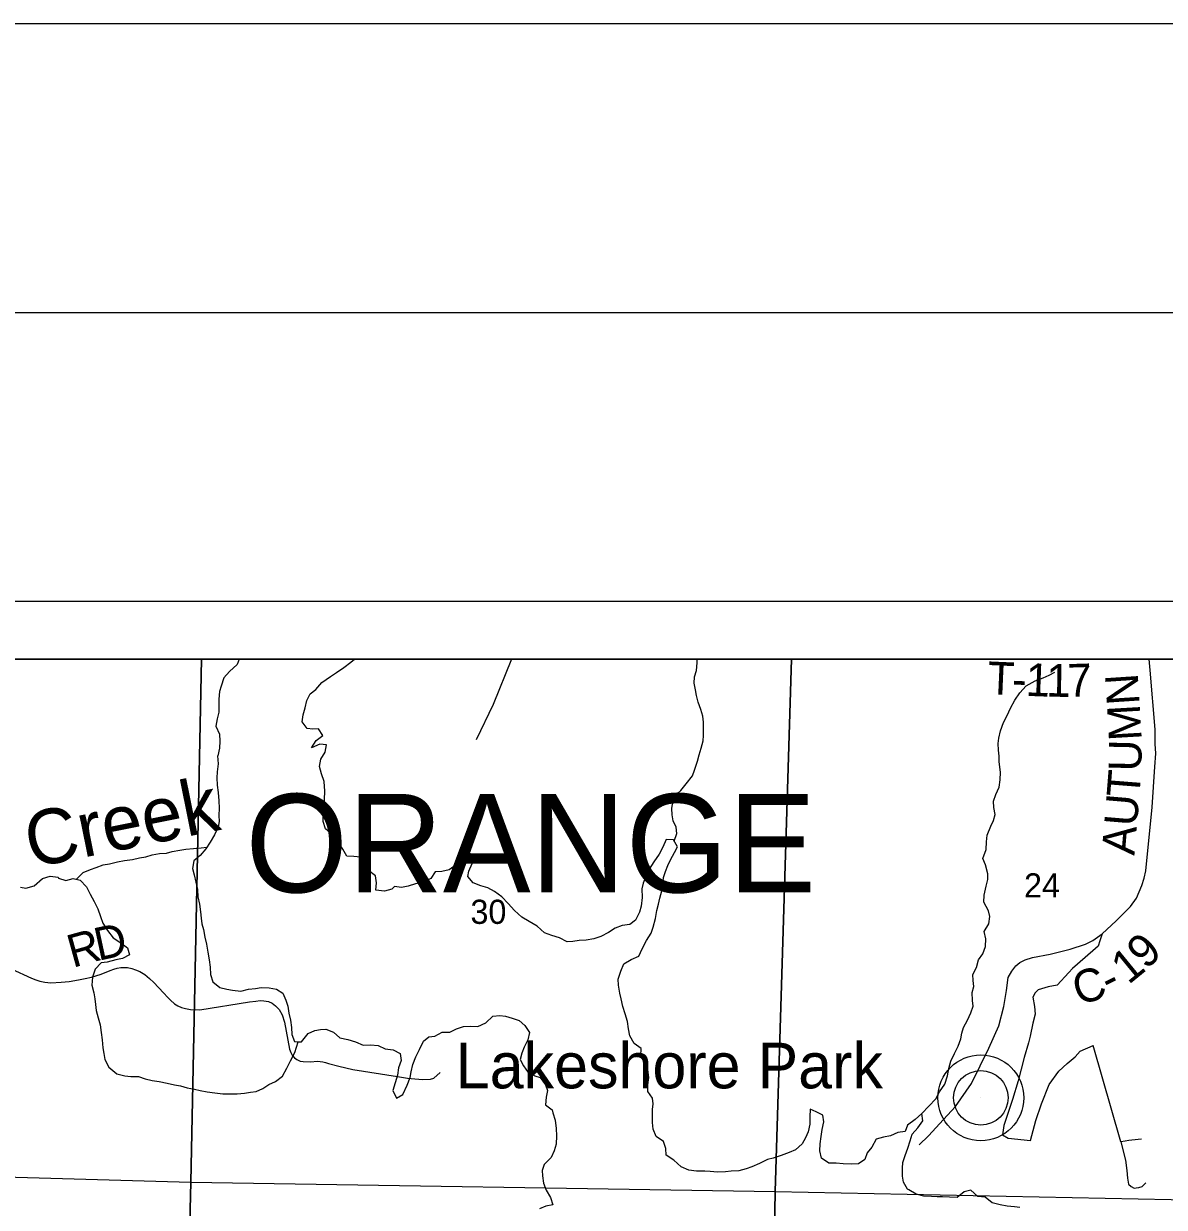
# Model space of a CAD drawing. Extents: x 0 to 34, y 0 to 22.
# Drawn here: x 4.316 to 6.292, y 19.951 to 22 of the extents above; entities that cross this region are included whole.
import ezdxf

# ---------------------------------------------------------------- set-up
doc = ezdxf.new("R2010")
doc.units = 0
for name, color, linetype in [('Default', 7, 'Continuous'), ('GM_X_Corporation', 7, 'Continuous'), ('GM_X_Corporation_Text', 7, 'Continuous'), ('GM_X_County_Road_Text', 7, 'Continuous'), ('GM_X_Interchange_Ramps', 7, 'Continuous'), ('GM_X_Interstate_Route', 7, 'Continuous'), ('GM_X_Major_Lake', 7, 'Continuous'), ('GM_X_Major_River', 7, 'Continuous'), ('GM_X_Minor_Lake', 7, 'Continuous'), ('GM_X_Section', 7, 'Continuous'), ('GM_X_Section_Text', 7, 'Continuous'), ('GM_X_State_Location', 7, 'Continuous'), ('GM_X_State_Shield', 7, 'Continuous'), ('GM_X_Township_Road_Text', 7, 'Continuous'), ('GM_X_Unincorporated_Location', 7, 'Continuous'), ('GM_X_US_Location', 7, 'Continuous'), ('SH_Border', 7, 'Continuous'), ('SH_Cut_Line', 7, 'Continuous'), ('SH_Data', 7, 'Continuous')]:
    doc.layers.add(name, color=color, linetype=linetype)

msp = doc.modelspace()

# ---------------------------------------------------------------- linework, layer by layer
at = {"layer": 'Default'}
for points in [[(4.6239, 20.9), (3.7753, 20.9), (3.7556, 20.0185), (4.6053, 19.9945)], [(5.6459, 20.9), (4.6239, 20.9), (4.6053, 19.9945), (5.6176, 19.9781)], [(6.6727, 20.9), (5.6459, 20.9), (5.6176, 19.9781), (6.6462, 19.9578)]]:
    msp.add_lwpolyline(points, close=True, dxfattribs=at)
at = {"layer": 'GM_X_Corporation'}
msp.add_lwpolyline([(5.8668, 20.0593), (5.8829, 20.0744), (5.9091, 20.103), (5.93, 20.1254), (5.9573, 20.1651), (5.9874, 20.2262), (6.0048, 20.265), (6.0134, 20.2985), (6.0184, 20.3265), (6.0212, 20.3488), (6.0273, 20.36), (6.0346, 20.369), (6.0415, 20.3747), (6.0504, 20.3794), (6.0631, 20.3834), (6.094, 20.389), (6.1284, 20.3979), (6.1552, 20.4067), (6.1675, 20.4131), (6.1757, 20.4188), (6.1841, 20.4246), (6.2081, 20.447), (6.233, 20.4716), (6.2431, 20.4859), (6.248, 20.4973), (6.2524, 20.508), (6.2565, 20.5207), (6.2594, 20.5336), (6.2705, 20.6434), (6.2749, 20.7136), (6.2765, 20.7368), (6.2759, 20.7531), (6.2755, 20.7781), (6.2668, 20.8811), (6.2652, 20.9)], dxfattribs=at)
at = {"layer": 'GM_X_Interchange_Ramps'}
msp.add_lwpolyline([(6.6698, 20.9), (2.1, 20.9), (2.1, 17.9098), (2.4376, 17.9025), (2.6711, 17.8975), (2.9484, 17.8857), (3.604, 17.8577), (3.7063, 17.8588), (3.7128, 17.9822), (4.1825, 17.9744), (4.4481, 17.9728), (4.5919, 17.9719), (4.9267, 17.9702), (4.9368, 17.9702), (4.994, 17.969), (5.3871, 17.9608), (5.6339, 17.9555), (6.0729, 17.9463), (6.24, 17.9427), (6.5943, 17.9356), (6.6079, 18.3189), (6.6258, 18.9603), (6.6304, 19.2166), (6.6438, 19.9593)], close=True, dxfattribs=at)
at = {"layer": 'GM_X_Interstate_Route'}
for points in [[(5.1608, 20.9), (5.1293, 20.8215), (5.0999, 20.7602)], [(6.1841, 20.4246), (6.1796, 20.4124), (6.177, 20.4031), (6.1676, 20.3948), (6.1324, 20.3644), (6.1262, 20.3577)], [(4.2946, 20.3639), (4.3294, 20.3474), (4.3372, 20.3446), (4.344, 20.3424), (4.3527, 20.3406), (4.3628, 20.3395), (4.3812, 20.3406), (4.3947, 20.342), (4.4107, 20.3448), (4.4225, 20.347), (4.4333, 20.3495), (4.4505, 20.3547), (4.4659, 20.361), (4.4722, 20.363), (4.4778, 20.3648), (4.4842, 20.366), (4.4902, 20.3662), (4.4961, 20.366), (4.5031, 20.3645), (4.5096, 20.3623), (4.517, 20.359), (4.5256, 20.3537), (4.534, 20.3472), (4.5413, 20.3402), (4.5583, 20.3222), (4.5658, 20.3141), (4.5701, 20.3095), (4.5771, 20.3031), (4.583, 20.3), (4.5896, 20.297), (4.5963, 20.2949), (4.6052, 20.2933), (4.6213, 20.293), (4.7073, 20.3067), (4.718, 20.3081), (4.7254, 20.3088), (4.732, 20.3084), (4.7399, 20.307), (4.7464, 20.3042), (4.7523, 20.3), (4.7586, 20.2932), (4.7638, 20.2844), (4.7679, 20.2713), (4.7764, 20.2246), (4.7786, 20.2188), (4.7812, 20.2142), (4.7848, 20.2097), (4.7889, 20.2067), (4.7946, 20.2041), (4.8, 20.2031), (4.8124, 20.2029), (4.8252, 20.2037), (4.8298, 20.2036), (4.8341, 20.203), (4.8386, 20.2019), (4.8442, 20.2001), (4.8619, 20.1952), (4.886, 20.1898), (4.9632, 20.1775), (4.9808, 20.1743), (4.9936, 20.1732), (5.0073, 20.1722), (5.0204, 20.1729), (5.0263, 20.1743), (5.0373, 20.1846)], [(6.1262, 20.3577), (6.1057, 20.3355), (6.0903, 20.3328), (6.0732, 20.3272), (6.0676, 20.3223), (6.0637, 20.3147), (6.0666, 20.2986), (6.0679, 20.2852), (6.064, 20.2697), (6.0594, 20.247), (6.056, 20.2356)], [(6.056, 20.2356), (6.0485, 20.2102), (6.0383, 20.1697), (6.0288, 20.1378), (6.0189, 20.1079), (6.0134, 20.0928), (6.011, 20.0764), (6.0212, 20.0708), (6.06, 20.0668)], [(6.06, 20.0668), (6.0689, 20.1013), (6.0788, 20.1303), (6.0923, 20.1638), (6.109, 20.1868), (6.1235, 20.1997), (6.137, 20.2115), (6.1455, 20.221), (6.1685, 20.2312)], [(6.2521, 20.0691), (6.235, 20.0671), (6.23, 20.0665), (6.2238, 20.0655), (6.2159, 20.0645), (6.1685, 20.2312)], [(6.2159, 20.0645), (6.2241, 20.0323), (6.2264, 20.0145), (6.2276, 20.0016), (6.2286, 19.9946), (6.2295, 19.991), (6.2339, 19.9867), (6.2395, 19.9838), (6.2429, 19.9848), (6.2476, 19.9853), (6.2529, 19.9872), (6.2568, 19.9904), (6.2595, 19.9935)]]:
    msp.add_lwpolyline(points, dxfattribs=at)
at = {"layer": 'GM_X_Minor_Lake'}
for points in [[(3.7556, 20.0185), (4.6053, 19.9945), (4.5812, 18.9996), (3.7421, 19.0151), (3.7574, 19.9211)], [(4.6053, 19.9945), (5.6176, 19.9781), (5.6006, 18.9822), (4.5812, 18.9996)], [(6.6462, 19.9578), (6.6311, 18.9612), (5.6006, 18.9822), (5.6176, 19.9781)]]:
    msp.add_lwpolyline(points, close=True, dxfattribs=at)
at = {"layer": 'GM_X_State_Location'}
msp.add_line((5.9737, 20.1405), (5.9737, 20.1405), dxfattribs=at)
at = {"layer": 'GM_X_State_Shield'}
for radius in [0.0744, 0.0472]:
    msp.add_circle((5.9737, 20.1405), radius, dxfattribs=at)
at = {"layer": 'GM_X_Township_Road_Text'}
for points in [[(5.4428, 20.5847), (5.4474, 20.5979), (5.4458, 20.6089), (5.4411, 20.6198), (5.4391, 20.6301), (5.4383, 20.6414), (5.4401, 20.6525), (5.4434, 20.6627), (5.454, 20.6723), (5.4634, 20.6838), (5.4743, 20.6979), (5.478, 20.7078), (5.4828, 20.7234), (5.4861, 20.734), (5.4894, 20.7458), (5.4931, 20.7584), (5.4934, 20.7678), (5.4932, 20.791), (5.4923, 20.8012), (5.4888, 20.8126), (5.4841, 20.8254), (5.481, 20.8372), (5.4798, 20.8466), (5.4774, 20.8584), (5.4781, 20.869), (5.481, 20.8804), (5.4824, 20.8937), (5.4824, 20.9)], [(5.8713, 20.1131), (5.8838, 20.1263), (5.8959, 20.1389), (5.9019, 20.1507), (5.9112, 20.1644), (5.916, 20.1785), (5.9182, 20.1914), (5.9215, 20.204), (5.9282, 20.2173), (5.9342, 20.2299), (5.939, 20.2428), (5.9408, 20.2523), (5.9434, 20.2622), (5.9509, 20.2752), (5.9565, 20.2877), (5.9606, 20.2992), (5.9593, 20.309), (5.9585, 20.3227), (5.9618, 20.3333), (5.9606, 20.3435), (5.9601, 20.3542), (5.9661, 20.366), (5.9697, 20.3793), (5.9772, 20.3896), (5.9817, 20.4025), (5.9823, 20.4158), (5.9796, 20.4287), (5.9878, 20.4416), (5.9892, 20.4546), (5.9868, 20.4644), (5.9791, 20.4791), (5.9794, 20.4913), (5.983, 20.5069), (5.9856, 20.5183), (5.9859, 20.5285), (5.9816, 20.5436), (5.9773, 20.555), (5.9829, 20.5702), (5.9835, 20.5835), (5.9845, 20.5953), (5.9913, 20.6109), (5.9957, 20.6208), (5.9983, 20.631), (5.9963, 20.6428), (5.9958, 20.6538), (5.9999, 20.6656), (6.0055, 20.6785), (6.0073, 20.6907), (6.0075, 20.7043), (6.0055, 20.7221), (6.0054, 20.732), (6.0041, 20.7422), (6.004, 20.7536), (6.0051, 20.7631), (6.0076, 20.776), (6.0132, 20.7901), (6.0192, 20.8023), (6.0252, 20.8149), (6.0326, 20.8286), (6.0413, 20.8416), (6.0525, 20.8538), (6.068, 20.8626), (6.0817, 20.8677), (6.0923, 20.8723), (6.1021, 20.8774)], [(4.4074, 20.5188), (4.419, 20.5305), (4.4315, 20.5359), (4.4413, 20.539), (4.4538, 20.5437), (4.4648, 20.5453), (4.4785, 20.5492), (4.4906, 20.5516), (4.5046, 20.5532), (4.5168, 20.5559), (4.5274, 20.5579), (4.5387, 20.5614), (4.5513, 20.5634), (4.5634, 20.5643), (4.5733, 20.567), (4.5865, 20.5691), (4.5968, 20.571), (4.6101, 20.5723), (4.6237, 20.5732), (4.6334, 20.5745)]]:
    msp.add_lwpolyline(points, dxfattribs=at)
at = {"layer": 'GM_X_Unincorporated_Location'}
for points in [[(4.6892, 20.9), (4.6856, 20.8905), (4.6725, 20.8785), (4.6628, 20.8674), (4.6581, 20.8533), (4.6552, 20.8437), (4.6543, 20.8304), (4.654, 20.821), (4.6543, 20.8084), (4.651, 20.7963), (4.649, 20.7841), (4.6553, 20.7701), (4.6559, 20.758), (4.6549, 20.7459), (4.6521, 20.7325)], [(4.8123, 20.8399), (4.822, 20.8476), (4.8324, 20.8595), (4.8475, 20.87), (4.8576, 20.8766), (4.8704, 20.8852), (4.8824, 20.8949), (4.8892, 20.9)], [(4.9536, 20.5019), (4.9408, 20.4983), (4.9259, 20.4999), (4.9268, 20.5125), (4.9255, 20.5246), (4.9135, 20.5343), (4.9073, 20.5459), (4.8995, 20.5572), (4.888, 20.5581), (4.8759, 20.5591), (4.8688, 20.5707), (4.8606, 20.5831), (4.8509, 20.5958), (4.8386, 20.6059), (4.835, 20.6187), (4.8347, 20.6324), (4.8357, 20.6441), (4.837, 20.657), (4.8375, 20.6711), (4.8365, 20.6878), (4.8321, 20.7013), (4.8284, 20.7138), (4.8305, 20.7267), (4.8383, 20.739), (4.8403, 20.7516), (4.8289, 20.7529), (4.8146, 20.7462), (4.8227, 20.7592), (4.834, 20.7678), (4.8266, 20.7794), (4.8171, 20.7785), (4.8072, 20.7798), (4.7986, 20.7915), (4.8003, 20.8036), (4.8035, 20.8158), (4.8067, 20.8284), (4.8123, 20.8399)], [(4.6521, 20.7325), (4.6517, 20.7325), (4.6527, 20.7189), (4.6514, 20.7048), (4.6508, 20.6946), (4.6514, 20.6817), (4.6528, 20.6688), (4.6542, 20.6548), (4.6544, 20.6419), (4.6542, 20.629), (4.6544, 20.6191), (4.6527, 20.6089), (4.6468, 20.5959), (4.639, 20.5832), (4.6316, 20.5717), (4.6219, 20.5598), (4.611, 20.5509), (4.6086, 20.5376), (4.6115, 20.5263), (4.6143, 20.5138), (4.6168, 20.5013), (4.6174, 20.4884), (4.6203, 20.4759), (4.622, 20.4627), (4.6234, 20.4513), (4.6247, 20.4415), (4.6275, 20.4317), (4.63, 20.4188), (4.6325, 20.4063), (4.635, 20.3927), (4.6371, 20.3795), (4.6388, 20.3666), (4.6398, 20.3541), (4.6438, 20.3413), (4.6558, 20.3312), (4.668, 20.3288), (4.6775, 20.3267), (4.6924, 20.325), (4.7056, 20.3283), (4.7174, 20.33), (4.7276, 20.3313), (4.7413, 20.3307), (4.7539, 20.3287), (4.765, 20.3216), (4.7698, 20.3096), (4.7734, 20.299), (4.7755, 20.2873), (4.7784, 20.2752), (4.7801, 20.262), (4.7807, 20.2502), (4.7851, 20.2378), (4.7914, 20.2375)], [(5.4423, 20.0327), (5.4289, 20.0412), (5.4283, 20.053), (5.4239, 20.065), (5.4112, 20.0736), (5.4065, 20.086), (5.4051, 20.0977), (5.4049, 20.1099), (5.4051, 20.1205), (5.4061, 20.13), (5.4052, 20.1398), (5.397, 20.1515), (5.3972, 20.1632), (5.3989, 20.1758), (5.3972, 20.1887), (5.3916, 20.1999), (5.385, 20.2131), (5.3855, 20.2256), (5.3736, 20.2345), (5.3661, 20.2477), (5.3633, 20.2598), (5.3615, 20.2727), (5.3579, 20.2859), (5.3539, 20.2983), (5.3506, 20.3119), (5.3486, 20.3218), (5.346, 20.3354), (5.3459, 20.346), (5.3502, 20.3597), (5.3553, 20.3723), (5.3681, 20.3801), (5.3813, 20.3857), (5.3872, 20.3986), (5.3946, 20.4128), (5.4027, 20.4258), (5.4063, 20.4358), (5.4103, 20.451), (5.4127, 20.4647), (5.4152, 20.4757), (5.4177, 20.4864), (5.4212, 20.499), (5.423, 20.5085), (5.4243, 20.5218), (5.4275, 20.5321), (5.4315, 20.5428), (5.4363, 20.5527), (5.4433, 20.5653), (5.4485, 20.5749), (5.4414, 20.5869), (5.4289, 20.5879), (5.423, 20.5745), (5.4168, 20.5623), (5.4071, 20.5488), (5.3993, 20.5362), (5.3935, 20.5239), (5.3887, 20.5121), (5.3866, 20.5022), (5.3869, 20.487), (5.3852, 20.4722), (5.3823, 20.4619), (5.3757, 20.4482), (5.3656, 20.4408), (5.3527, 20.4387), (5.3406, 20.4339), (5.3286, 20.4269), (5.3154, 20.4195), (5.3033, 20.4155), (5.2904, 20.4137), (5.2782, 20.4128), (5.2669, 20.4111), (5.2574, 20.4105), (5.2443, 20.4175), (5.2306, 20.4215), (5.2179, 20.4262), (5.2052, 20.4374), (5.1914, 20.4459), (5.1787, 20.4533), (5.166, 20.4648), (5.1551, 20.4771), (5.1443, 20.4883), (5.1316, 20.4976), (5.1201, 20.5039), (5.1075, 20.5075), (5.0945, 20.5126), (5.0855, 20.5234), (5.0869, 20.5329), (5.0928, 20.5459), (5.1002, 20.5589), (5.0902, 20.5626), (5.0767, 20.554), (5.0669, 20.5447), (5.053, 20.5354), (5.0405, 20.5325), (5.0288, 20.5316), (5.0214, 20.5201), (5.0085, 20.5138), (4.9945, 20.5109), (4.9817, 20.5069), (4.9703, 20.5048), (4.9581, 20.5062), (4.9536, 20.5019)], [(4.7914, 20.2375), (4.7972, 20.2372), (4.8088, 20.2518), (4.8205, 20.2569), (4.8299, 20.2586), (4.8394, 20.2595), (4.8528, 20.254), (4.8636, 20.2444), (4.8774, 20.2415), (4.8907, 20.2376), (4.9041, 20.2317), (4.9167, 20.232), (4.93, 20.231), (4.9423, 20.2255), (4.956, 20.2235), (4.9679, 20.2172), (4.97, 20.2051), (4.9653, 20.1922), (4.9636, 20.1796), (4.9596, 20.1666), (4.9556, 20.1529), (4.9619, 20.1397), (4.9725, 20.1464), (4.9802, 20.1624), (4.9853, 20.1758), (4.987, 20.1853), (4.9899, 20.1979), (4.995, 20.2116), (5.0016, 20.2239), (5.0082, 20.2384), (5.0179, 20.2461), (5.0282, 20.2474), (5.0406, 20.2541), (5.0539, 20.2543), (5.0656, 20.2602), (5.0777, 20.2638), (5.0895, 20.2644), (5.1024, 20.2642), (5.1164, 20.2705), (5.1287, 20.2817), (5.1409, 20.2831), (5.1504, 20.2821), (5.1622, 20.2785), (5.1741, 20.2741), (5.1841, 20.2659), (5.1919, 20.2536), (5.1891, 20.2406), (5.1829, 20.228), (5.1785, 20.218), (5.176, 20.2066), (5.1819, 20.1961)], [(5.1819, 20.1961), (5.19, 20.1845), (5.2012, 20.1786), (5.2107, 20.1757), (5.2197, 20.163), (5.2233, 20.1532), (5.2212, 20.1417), (5.2195, 20.1284), (5.2314, 20.1195)], [(5.2314, 20.1195), (5.2323, 20.1146), (5.2363, 20.1018), (5.238, 20.0874), (5.2386, 20.0749), (5.2385, 20.0605), (5.2349, 20.0486), (5.2298, 20.0372), (5.2174, 20.0252), (5.2138, 20.0149), (5.2143, 20.0054), (5.2161, 19.9926), (5.2212, 19.9809), (5.2282, 19.9681), (5.2323, 19.9553), (5.2201, 19.9532), (5.2092, 19.9481)], [(5.8465, 19.9821), (5.8399, 19.9942), (5.8378, 20.0051), (5.8379, 20.0188), (5.8389, 20.0283), (5.8429, 20.0405), (5.8472, 20.0535), (5.8516, 20.0661), (5.8548, 20.0775), (5.8645, 20.0887), (5.8731, 20.1006), (5.8713, 20.1131), (5.8597, 20.103), (5.8466, 20.0933), (5.8429, 20.0822), (5.8301, 20.0805), (5.8172, 20.0746), (5.8051, 20.0725), (5.7926, 20.0689), (5.7852, 20.0551), (5.777, 20.0455), (5.7727, 20.034), (5.7618, 20.0263), (5.7492, 20.0257), (5.7352, 20.0262), (5.7234, 20.0275), (5.7104, 20.0273), (5.6977, 20.0362), (5.6949, 20.0487), (5.6954, 20.0608), (5.6971, 20.0737), (5.6992, 20.0859), (5.702, 20.0989), (5.6999, 20.1102), (5.6888, 20.1165), (5.6781, 20.1208), (5.6775, 20.1076), (5.6778, 20.0947), (5.6745, 20.0817), (5.6702, 20.071), (5.6643, 20.0611), (5.6526, 20.0502), (5.6417, 20.0459), (5.6281, 20.0407), (5.6141, 20.0359), (5.6043, 20.0335), (5.5903, 20.0268), (5.5771, 20.0213), (5.5673, 20.0177), (5.5544, 20.0141), (5.5411, 20.0135), (5.5313, 20.0122), (5.5176, 20.012), (5.505, 20.0129), (5.4955, 20.0135), (5.481, 20.0136), (5.4681, 20.0153), (5.4547, 20.0208), (5.4423, 20.0327)], [(6.0413, 19.9505), (6.0318, 19.9515), (6.0192, 19.9532), (6.007, 19.9552), (5.9933, 19.9588), (5.9813, 19.9685), (5.9684, 19.9698), (5.9564, 19.9809), (5.9447, 19.9777), (5.9327, 19.968), (5.9197, 19.9686), (5.9076, 19.9691), (5.8981, 19.969), (5.8885, 19.9699), (5.8752, 19.9701), (5.8619, 19.9737), (5.8492, 19.981), (5.8465, 19.9821)]]:
    msp.add_lwpolyline(points, dxfattribs=at)
at = {"layer": 'GM_X_US_Location'}
for points in [[(4.3104, 20.505), (4.3199, 20.5032), (4.3343, 20.5073), (4.3485, 20.5204), (4.3621, 20.5244), (4.3755, 20.5224)], [(4.3755, 20.5224), (4.3763, 20.5205), (4.3889, 20.5165), (4.4017, 20.5201), (4.4139, 20.5173), (4.4248, 20.5057), (4.4314, 20.4933), (4.4381, 20.4802), (4.4444, 20.4674), (4.4488, 20.4542), (4.4532, 20.4428), (4.461, 20.4301), (4.4711, 20.4177), (4.4826, 20.4099), (4.4957, 20.3999), (4.4993, 20.3882), (4.4869, 20.3816), (4.4759, 20.3791), (4.4604, 20.3754), (4.4505, 20.3741), (4.4401, 20.363), (4.4354, 20.3492), (4.4341, 20.3355), (4.4373, 20.3223), (4.439, 20.3117), (4.4403, 20.3019), (4.4417, 20.2917), (4.4449, 20.2792), (4.4485, 20.2671), (4.4503, 20.2535), (4.452, 20.241), (4.4534, 20.227), (4.4551, 20.2171), (4.4564, 20.2069), (4.4634, 20.1938), (4.4773, 20.1822), (4.4914, 20.1787), (4.5017, 20.1773), (4.5147, 20.1772), (4.5265, 20.1732), (4.5387, 20.1707), (4.5505, 20.1686), (4.5643, 20.1658), (4.5772, 20.163), (4.5879, 20.1613), (4.599, 20.1577), (4.6116, 20.1556), (4.6219, 20.1531), (4.6337, 20.1507), (4.647, 20.149), (4.6611, 20.1473), (4.6741, 20.1472), (4.6858, 20.1473), (4.6987, 20.1487), (4.7086, 20.15), (4.7185, 20.1517), (4.7302, 20.1568), (4.7407, 20.1634), (4.752, 20.1689), (4.764, 20.1782), (4.7718, 20.1916), (4.7784, 20.2043), (4.7858, 20.2188), (4.7886, 20.2283), (4.7914, 20.2375)]]:
    msp.add_lwpolyline(points, dxfattribs=at)
at = {"layer": 'SH_Border'}
msp.add_lwpolyline([(1.5, 21.5), (33.5, 21.5), (33.5, 0.5), (1.5, 0.5)], close=True, dxfattribs=at)
at = {"layer": 'SH_Cut_Line'}
for points in [[(0, 0), (34, 0), (34, 22), (0, 22)], [(8.9, 17.8921), (8.9, 20.9), (2.1, 20.9), (2.1, 17.9098), (2.4376, 17.9025), (2.6711, 17.8975), (2.9484, 17.8857), (3.604, 17.8577), (3.7063, 17.8588), (3.7128, 17.9822), (4.1825, 17.9744), (4.4481, 17.9728), (4.5919, 17.9719), (4.9267, 17.9702), (4.9368, 17.9702), (4.994, 17.969), (5.3871, 17.9608), (5.6339, 17.9555), (6.0729, 17.9463), (6.24, 17.9427), (6.5943, 17.9356), (7.6027, 17.9156), (8.3297, 17.9059), (8.5492, 17.9006)]]:
    msp.add_lwpolyline(points, close=True, dxfattribs=at)
at = {"layer": 'SH_Data'}
for p, q in [((2, 21), (9, 21)), ((2.1, 20.9), (8.9, 20.9))]:
    msp.add_line(p, q, dxfattribs=at)

# ---------------------------------------------------------------- texts
at = {"layer": 'GM_X_Corporation_Text'}
msp.add_text('Lakeshore Park', height=0.078977, rotation=0, dxfattribs=at).set_placement((5.0644, 20.1569))
at = {"layer": 'GM_X_County_Road_Text'}
for s, p in [('24', (6.0485, 20.4873)), ('30', (5.0898, 20.4416))]:
    msp.add_text(s, height=0.04186, rotation=0, dxfattribs=at).set_placement(p)
at = {"layer": 'GM_X_Major_Lake'}
for s, rotation, p in [('N', 93.7532, (6.2489, 20.8221)), ('M', 93.2844, (6.2525, 20.76)), ('U', 88.7388, (6.2515, 20.7051)), ('T', 85.4755, (6.248, 20.6592)), ('U', 85.2261, (6.2438, 20.6091)), ('A', 85.2297, (6.2396, 20.5593)), ('9', 44.1561, (6.2603, 20.361)), ('1', 39.3224, (6.2293, 20.3353)), ('C', 17.687, (6.1434, 20.2998)), ('-', 26.0766, (6.1963, 20.3173))]:
    msp.add_text(s, height=0.0568, rotation=rotation, dxfattribs=at).set_placement(p)
at = {"layer": 'GM_X_Major_River'}
msp.add_text('Creek', height=0.0947, rotation=11.4091, dxfattribs=at).set_placement((4.3288, 20.538))
at = {"layer": 'GM_X_Section'}
for s, rotation, p in [('T', 357.4727, (5.9842, 20.8393)), ('1', 357.9312, (6.0505, 20.8364)), ('1', 358.9515, (6.0865, 20.8351)), ('7', 1.7317, (6.1245, 20.8345)), ('-', 357.5755, (6.0268, 20.8374)), ('R', 15.4961, (4.4009, 20.3653)), ('D', 12.208, (4.4451, 20.3775))]:
    msp.add_text(s, height=0.0568, rotation=rotation, dxfattribs=at).set_placement(p)
at = {"layer": 'GM_X_Section_Text'}
msp.add_text('ORANGE', height=0.17045, rotation=0, dxfattribs=at).set_placement((4.7002, 20.4961))

doc.saveas('drawing.dxf')
